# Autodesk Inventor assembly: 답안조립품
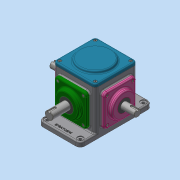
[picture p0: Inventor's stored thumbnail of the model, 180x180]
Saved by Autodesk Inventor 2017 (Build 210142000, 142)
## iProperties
Part Number: 답안조립품
Material: 일반
Document SubType Name: Assembly
Designer: MRC
Mass: 3235.88 g
Surface Area: 2651.69 cm^2
Volume: 866.536 cm^3
Density: 3.73427 g/cm^3
Author: MRC
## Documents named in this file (16)
- C:\Users\MRC\Desktop\620307V1010\답안조립품.iam
- C:\Users\MRC\Desktop\620307V1010\개스킷.ipt
- C:\Users\MRC\Desktop\620307V1010\메인베벨기어.ipt
- C:\Users\MRC\Desktop\620307V1010\메인축.ipt
- C:\Users\MRC\Desktop\620307V1010\메인커버.ipt
- C:\Users\MRC\Desktop\620307V1010\베어링 6203.ipt
- C:\Users\MRC\Desktop\620307V1010\베어링 6204.ipt
- C:\Users\MRC\Desktop\620307V1010\본체.ipt
- C:\Users\MRC\Desktop\620307V1010\볼트 M4.ipt
- C:\Users\MRC\Desktop\620307V1010\상부커버.ipt
- C:\Users\MRC\Desktop\620307V1010\서브베벨기어.ipt
- C:\Users\MRC\Desktop\620307V1010\서브축.ipt
- C:\Users\MRC\Desktop\620307V1010\서브커버.ipt
- C:\Users\MRC\Desktop\620307V1010\오일 실 17 32 8.ipt
- C:\Users\MRC\Desktop\620307V1010\오일 실 20 35 8.ipt
- C:\Users\MRC\Desktop\620307V1010\키 4x4.ipt
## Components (1 placed, 1 different names)
1. 개스킷:1
